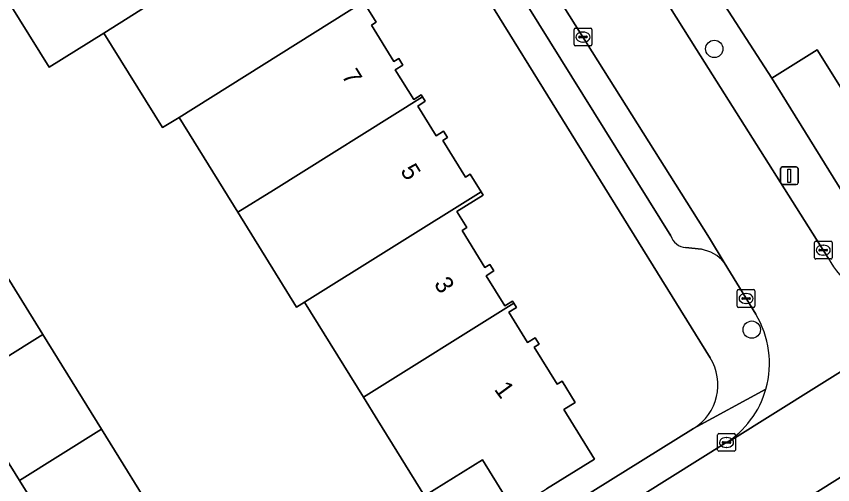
# Model space of a CAD drawing. Extents: x 157767 to 159172, y 387839 to 389425.
# Drawn here: x 158542.27 to 158588.4, y 388044.19 to 388070.65 of the extents above; entities that cross this region are included whole.
import ezdxf

# ---------------------------------------------------------------- set-up
doc = ezdxf.new("R2010")
doc.units = 0
for name, color, linetype in [('IMGEO_Boom', 7, 'Continuous'), ('IMGEO_Erf', 7, 'Continuous'), ('IMGEO_Kolk', 7, 'Continuous'), ('IMGEO_Lichtmast', 7, 'Continuous'), ('IMGEO_Pand', 7, 'Continuous'), ('IMGEO_Pand_nummerreeks', 7, 'Continuous'), ('IMGEO_Parkeervlak_open', 7, 'Continuous'), ('IMGEO_Rijbaan_lokaal_open', 7, 'Continuous'), ('IMGEO_Voetpad_open', 7, 'Continuous')]:
    doc.layers.add(name, color=color, linetype=linetype)

msp = doc.modelspace()

# ---------------------------------------------------------------- linework, layer by layer
at = {"layer": 'IMGEO_Boom'}
for centre in [(158581.714, 388068.809), (158583.832, 388052.949)]:
    msp.add_circle(centre, 0.489, dxfattribs=at)
at = {"layer": 'IMGEO_Erf'}
for points in [[(158581.483, 388051.362), (158560.399, 388085.371)], [(158570.354, 388042.793), (158568.615, 388045.599), (158565.338, 388043.57), (158562.706, 388047.821), (158561.891, 388049.137), (158558.564, 388054.508), (158558.102, 388054.219), (158554.783, 388059.578), (158551.465, 388064.936), (158550.538, 388064.358), (158547.208, 388069.7), (158544.119, 388067.774), (158540.75, 388073.178)], [(158561.897, 388071.468), (158562.608, 388070.322), (158562.335, 388070.153), (158563.614, 388068.09), (158563.885, 388068.258), (158564.111, 388067.894), (158563.687, 388067.629), (158564.729, 388065.948), (158565.153, 388066.21), (158565.22, 388066.102), (158565.379, 388065.846), (158564.953, 388065.581), (158565.995, 388063.9), (158566.42, 388064.163), (158566.646, 388063.797), (158566.374, 388063.628), (158567.652, 388061.566), (158567.924, 388061.734), (158568.541, 388060.738), (158568.661, 388060.545), (158567.174, 388059.625), (158567.738, 388058.716), (158567.463, 388058.545), (158568.755, 388056.462), (158569.028, 388056.632), (158569.257, 388056.262), (158568.827, 388055.996), (158569.88, 388054.298), (158570.308, 388054.564), (158570.383, 388054.442), (158570.537, 388054.194), (158570.107, 388053.928), (158571.16, 388052.23), (158571.588, 388052.496), (158571.816, 388052.127), (158571.541, 388051.956), (158572.833, 388049.873), (158573.108, 388050.042), (158573.852, 388048.842), (158573.206, 388048.442), (158574.944, 388045.637), (158572.223, 388043.951)], [(158606.501, 388070.878), (158607.378, 388069.481), (158602.662, 388066.524), (158602.252, 388066.267), (158599.852, 388070.093), (158595.508, 388067.368), (158595.241, 388067.201), (158594.284, 388068.725), (158589.446, 388065.691), (158587.528, 388068.75), (158584.968, 388067.145), (158590.08, 388058.884)], [(158540.442, 388058.034), (158543.761, 388052.683), (158547.077, 388047.335), (158550.419, 388041.947), (158555.234, 388034.183), (158556.403, 388032.356), (158573.012, 388042.677), (158580.545, 388047.358)]]:
    msp.add_lwpolyline(points, dxfattribs=at)
msp.add_arc((158579.008, 388049.83), 2.911, 301.8764, 31.7543, dxfattribs=at)
at = {"layer": 'IMGEO_Kolk'}
for p, q in [((158573.792, 388069.05), (158573.792, 388069.902)), ((158573.867, 388069.976), (158574.719, 388069.976)), ((158574.793, 388069.902), (158574.793, 388069.05)), ((158574.051, 388069.47), (158574.051, 388069.482)), ((158574.489, 388069.433), (158574.091, 388069.433)), ((158574.094, 388069.519), (158574.492, 388069.519)), ((158574.28, 388069.756), (158574.305, 388069.756)), ((158574.535, 388069.482), (158574.535, 388069.47)), ((158574.719, 388068.976), (158573.867, 388068.976)), ((158574.303, 388069.196), (158574.278, 388069.196)), ((158587.368, 388057.014), (158587.368, 388057.866)), ((158587.443, 388057.94), (158588.295, 388057.94)), ((158588.369, 388057.866), (158588.369, 388057.014)), ((158587.627, 388057.434), (158587.627, 388057.446)), ((158588.065, 388057.397), (158587.667, 388057.397)), ((158587.67, 388057.483), (158588.068, 388057.483)), ((158587.856, 388057.72), (158587.881, 388057.72)), ((158588.111, 388057.446), (158588.111, 388057.434)), ((158588.295, 388056.94), (158587.443, 388056.94)), ((158587.879, 388057.16), (158587.854, 388057.16)), ((158583.01, 388054.282), (158583.01, 388055.134)), ((158583.085, 388055.208), (158583.937, 388055.208)), ((158584.011, 388055.134), (158584.011, 388054.282)), ((158583.269, 388054.702), (158583.269, 388054.714)), ((158583.707, 388054.665), (158583.309, 388054.665)), ((158583.312, 388054.751), (158583.71, 388054.751)), ((158583.498, 388054.988), (158583.523, 388054.988)), ((158583.753, 388054.714), (158583.753, 388054.702)), ((158583.937, 388054.208), (158583.085, 388054.208)), ((158583.521, 388054.428), (158583.496, 388054.428)), ((158581.904, 388046.151), (158581.904, 388047.003)), ((158581.979, 388047.077), (158582.831, 388047.077)), ((158582.392, 388046.857), (158582.417, 388046.857)), ((158582.905, 388047.003), (158582.905, 388046.151)), ((158582.163, 388046.571), (158582.163, 388046.583)), ((158582.601, 388046.534), (158582.203, 388046.534)), ((158582.206, 388046.62), (158582.604, 388046.62)), ((158582.415, 388046.297), (158582.39, 388046.297)), ((158582.647, 388046.583), (158582.647, 388046.571)), ((158582.831, 388046.077), (158581.979, 388046.077))]:
    msp.add_line(p, q, dxfattribs=at)
for points in [[(158573.792, 388069.05), (158573.792, 388069.902)], [(158573.867, 388069.976), (158574.719, 388069.976)], [(158574.793, 388069.902), (158574.793, 388069.05)], [(158574.719, 388068.976), (158573.867, 388068.976)], [(158587.368, 388057.014), (158587.368, 388057.866)], [(158587.443, 388057.94), (158588.295, 388057.94)], [(158588.369, 388057.866), (158588.369, 388057.014)], [(158588.295, 388056.94), (158587.443, 388056.94)], [(158583.01, 388054.282), (158583.01, 388055.134)], [(158583.085, 388055.208), (158583.937, 388055.208)], [(158584.011, 388055.134), (158584.011, 388054.282)], [(158583.937, 388054.208), (158583.085, 388054.208)], [(158581.904, 388046.151), (158581.904, 388047.003)], [(158581.979, 388047.077), (158582.831, 388047.077)], [(158582.905, 388047.003), (158582.905, 388046.151)], [(158582.831, 388046.077), (158581.979, 388046.077)]]:
    msp.add_lwpolyline(points, dxfattribs=at)
for centre, radius, start, end in [((158573.869, 388069.9), 0.0765, 91.552, 178.448), ((158573.869, 388069.9), 0.0765, 91.552, 178.448), ((158574.717, 388069.9), 0.0765, 1.552, 88.448), ((158574.717, 388069.9), 0.0765, 1.552, 88.448), ((158574.091, 388069.479), 0.0403, 85.8775, 175.7526), ((158574.088, 388069.469), 0.0366, 178.938, 274.7102), ((158574.492, 388069.476), 0.043, 264.8664, 352.4533), ((158574.496, 388069.481), 0.0386, 1.7309, 96.639), ((158573.869, 388069.052), 0.0765, 181.552, 268.448), ((158573.869, 388069.052), 0.0765, 181.552, 268.448), ((158574.717, 388069.052), 0.0765, 271.552, 358.448), ((158574.717, 388069.052), 0.0765, 271.552, 358.448), ((158587.445, 388057.864), 0.0765, 91.552, 178.448), ((158587.445, 388057.864), 0.0765, 91.552, 178.448), ((158588.293, 388057.864), 0.0765, 1.552, 88.448), ((158588.293, 388057.864), 0.0765, 1.552, 88.448), ((158587.667, 388057.443), 0.0403, 85.8775, 175.7526), ((158587.664, 388057.433), 0.0366, 178.938, 274.7102), ((158588.068, 388057.44), 0.043, 264.8664, 352.4533), ((158588.072, 388057.445), 0.0386, 1.7309, 96.639), ((158587.445, 388057.016), 0.0765, 181.552, 268.448), ((158587.445, 388057.016), 0.0765, 181.552, 268.448), ((158588.293, 388057.016), 0.0765, 271.552, 358.448), ((158588.293, 388057.016), 0.0765, 271.552, 358.448), ((158583.087, 388055.132), 0.0765, 91.552, 178.448), ((158583.087, 388055.132), 0.0765, 91.552, 178.448), ((158583.935, 388055.132), 0.0765, 1.552, 88.448), ((158583.935, 388055.132), 0.0765, 1.552, 88.448), ((158583.309, 388054.711), 0.0403, 85.8775, 175.7526), ((158583.306, 388054.701), 0.0366, 178.938, 274.7102), ((158583.71, 388054.708), 0.043, 264.8664, 352.4533), ((158583.714, 388054.713), 0.0386, 1.7309, 96.639), ((158583.087, 388054.284), 0.0765, 181.552, 268.448), ((158583.087, 388054.284), 0.0765, 181.552, 268.448), ((158583.935, 388054.284), 0.0765, 271.552, 358.448), ((158583.935, 388054.284), 0.0765, 271.552, 358.448), ((158581.981, 388047.001), 0.0765, 91.552, 178.448), ((158581.981, 388047.001), 0.0765, 91.552, 178.448), ((158582.829, 388047.001), 0.0765, 1.552, 88.448), ((158582.829, 388047.001), 0.0765, 1.552, 88.448), ((158582.203, 388046.58), 0.0403, 85.8775, 175.7526), ((158582.2, 388046.57), 0.0366, 178.938, 274.7102), ((158582.604, 388046.577), 0.043, 264.8664, 352.4533), ((158582.608, 388046.582), 0.0386, 1.7309, 96.639), ((158581.981, 388046.153), 0.0765, 181.552, 268.448), ((158581.981, 388046.153), 0.0765, 181.552, 268.448), ((158582.829, 388046.153), 0.0765, 271.552, 358.448), ((158582.829, 388046.153), 0.0765, 271.552, 358.448)]:
    msp.add_arc(centre, radius, start, end, dxfattribs=at)
for centre, major_axis, ratio, start_param, end_param in [((158574.279, 388069.476), (-0.387, 0.002), 0.722429, 4.712389, 7.853982), ((158574.304, 388069.476), (-0.39, 0.002), 0.717154, 1.570796, 4.712389), ((158587.855, 388057.44), (-0.387, 0.002), 0.722429, 4.712389, 7.853982), ((158587.88, 388057.44), (-0.39, 0.002), 0.717154, 1.570796, 4.712389), ((158583.497, 388054.708), (-0.387, 0.002), 0.722429, 4.712389, 7.853982), ((158583.522, 388054.708), (-0.39, 0.002), 0.717154, 1.570796, 4.712389), ((158582.391, 388046.577), (-0.387, 0.002), 0.722429, 4.712389, 7.853982), ((158582.416, 388046.577), (-0.39, 0.002), 0.717154, 1.570796, 4.712389)]:
    msp.add_ellipse(centre, major_axis=major_axis, ratio=ratio, start_param=start_param, end_param=end_param, dxfattribs=at)
at = {"layer": 'IMGEO_Lichtmast'}
for p, q in [((158585.454, 388061.244), (158585.454, 388062.044)), ((158585.454, 388062.044), (158585.454, 388061.244)), ((158585.554, 388062.144), (158586.344, 388062.144)), ((158586.344, 388062.144), (158585.554, 388062.144)), ((158586.444, 388062.044), (158586.444, 388061.244)), ((158586.444, 388061.244), (158586.444, 388062.044)), ((158586.344, 388061.144), (158585.554, 388061.144)), ((158585.554, 388061.144), (158586.344, 388061.144))]:
    msp.add_line(p, q, dxfattribs=at)
msp.add_lwpolyline([(158585.874, 388062.019), (158586.024, 388062.019), (158586.024, 388061.269), (158585.874, 388061.269), (158585.874, 388062.019)], dxfattribs=at)
for centre, start, end in [((158585.554, 388062.044), 90, 180), ((158585.554, 388062.044), 90, 180), ((158586.344, 388062.044), 0, 90), ((158586.344, 388062.044), 360, 90), ((158585.554, 388061.244), 180, 270), ((158585.554, 388061.244), 180, 270), ((158586.344, 388061.244), 270, 0), ((158586.344, 388061.244), 270, 0)]:
    msp.add_arc(centre, 0.1, start, end, dxfattribs=at)
at = {"layer": 'IMGEO_Pand'}
for points in [[(158558.596, 388076.799), (158558.542, 388076.887), (158558.117, 388076.625), (158557.075, 388078.306), (158557.5, 388078.57), (158557.274, 388078.935), (158557.002, 388078.767), (158555.724, 388080.83), (158555.997, 388080.999), (158555.259, 388082.188), (158551.008, 388079.556), (158546.824, 388076.965), (158543.839, 388075.104), (158540.75, 388073.178), (158544.119, 388067.774), (158547.208, 388069.7), (158550.177, 388071.551)], [(158551.465, 388064.936), (158561.897, 388071.468), (158561.312, 388072.41), (158561.041, 388072.243), (158559.762, 388074.305), (158560.034, 388074.474), (158559.808, 388074.84), (158559.384, 388074.577), (158558.342, 388076.258), (158558.767, 388076.523), (158558.596, 388076.799), (158550.177, 388071.551), (158547.208, 388069.7), (158550.538, 388064.358)], [(158590.193, 388075.903), (158585.3, 388072.835), (158584.145, 388074.678), (158581.379, 388072.944), (158581.281, 388072.883), (158584.968, 388067.145), (158587.528, 388068.75), (158589.446, 388065.691), (158594.284, 388068.725), (158594.557, 388068.896)], [(158565.22, 388066.102), (158565.153, 388066.21), (158564.729, 388065.948), (158563.687, 388067.629), (158564.111, 388067.894), (158563.885, 388068.258), (158563.614, 388068.09), (158562.335, 388070.153), (158562.608, 388070.322), (158561.897, 388071.468), (158551.465, 388064.936), (158554.783, 388059.578), (158556.813, 388060.835)], [(158568.541, 388060.738), (158567.924, 388061.734), (158567.652, 388061.566), (158566.374, 388063.628), (158566.646, 388063.797), (158566.42, 388064.163), (158565.995, 388063.9), (158564.953, 388065.581), (158565.379, 388065.846), (158565.22, 388066.102), (158556.813, 388060.835), (158554.783, 388059.578), (158558.102, 388054.219), (158558.564, 388054.508)], [(158570.383, 388054.442), (158570.308, 388054.564), (158569.88, 388054.298), (158568.827, 388055.996), (158569.257, 388056.262), (158569.028, 388056.632), (158568.755, 388056.462), (158567.463, 388058.545), (158567.738, 388058.716), (158567.174, 388059.625), (158568.661, 388060.545), (158568.541, 388060.738), (158558.564, 388054.508), (158561.891, 388049.137)], [(158539.118, 388049.775), (158543.761, 388052.683), (158540.442, 388058.034), (158535.788, 388055.115)], [(158570.383, 388054.442), (158561.891, 388049.137), (158562.706, 388047.821), (158565.338, 388043.57), (158568.615, 388045.599), (158570.354, 388042.793), (158572.223, 388043.951), (158574.944, 388045.637), (158573.206, 388048.442), (158573.852, 388048.842), (158573.108, 388050.042), (158572.833, 388049.873), (158571.541, 388051.956), (158571.816, 388052.127), (158571.588, 388052.496), (158571.16, 388052.23), (158570.107, 388053.928), (158570.537, 388054.194)], [(158542.447, 388044.435), (158547.077, 388047.335), (158543.761, 388052.683), (158539.118, 388049.775)], [(158542.447, 388044.435), (158545.856, 388038.968), (158550.419, 388041.947), (158547.077, 388047.335)]]:
    msp.add_lwpolyline(points, close=True, dxfattribs=at)
at = {"layer": 'IMGEO_Parkeervlak_open'}
for points in [[(158582.268, 388056.746), (158581.434, 388058.111), (158570.744, 388075.126), (158569.941, 388076.402), (158568.599, 388078.534), (158562.853, 388087.665)], [(158563.093, 388084.206), (158579.251, 388058.252)], [(158580.093, 388057.584), (158580.982, 388057.488)]]:
    msp.add_lwpolyline(points, dxfattribs=at)
for centre, radius, start, end in [((158580.172, 388058.548), 0.967, 197.8173, 265.3293), ((158580.594, 388055.33), 2.193, 40.2258, 79.8058)]:
    msp.add_arc(centre, radius, start, end, dxfattribs=at)
at = {"layer": 'IMGEO_Rijbaan_lokaal_open'}
for points in [[(158580.717, 388068.777), (158574.233, 388079.1), (158569.941, 388076.402), (158570.744, 388075.126), (158581.434, 388058.111), (158582.268, 388056.746), (158584.053, 388053.823)], [(158588.162, 388056.973), (158580.717, 388068.777)], [(158582.332, 388046.529), (158582.556, 388046.64), (158595.192, 388054.536)], [(158541.291, 388022.91), (158556.403, 388032.356), (158555.234, 388034.183), (158549.918, 388030.869), (158547.042, 388035.482), (158547.753, 388035.925), (158545.856, 388038.968), (158542.447, 388044.435), (158539.118, 388049.775)]]:
    msp.add_lwpolyline(points, dxfattribs=at)
msp.add_lwpolyline([(158602.47, 388053.168), (158607.134, 388056.097), (158604.468, 388060.381), (158598.186, 388056.371), (158595.192, 388054.536), (158582.556, 388046.64), (158582.332, 388046.529), (158565.577, 388036.046), (158560.3, 388032.761), (158562.987, 388028.446), (158574.586, 388035.66), (158586.389, 388043.071)], close=True, dxfattribs=at)
for centre, radius, start, end in [((158593.035, 388059.692), 5.58, 209.1561, 231.9393), ((158579.495, 388051.045), 5.338, 344.2276, 31.3644), ((158579.509, 388051.043), 5.324, 302.0232, 344.2071)]:
    msp.add_arc(centre, radius, start, end, dxfattribs=at)
at = {"layer": 'IMGEO_Voetpad_open'}
for points in [[(158543.728, 388114.955), (158550.45, 388104.152), (158551.851, 388101.897), (158553.86, 388098.665), (158555.739, 388095.641), (158557.163, 388093.348), (158558.904, 388090.545), (158556.64, 388089.139), (158554.172, 388087.608), (158555.818, 388084.922), (158556.878, 388083.191), (158560.399, 388085.371), (158581.483, 388051.362)], [(158579.251, 388058.252), (158563.093, 388084.206)], [(158584.968, 388067.145), (158581.281, 388072.883), (158581.379, 388072.944), (158574.516, 388084.034), (158572.668, 388082.532), (158572.243, 388082.269), (158572.893, 388081.234), (158574.233, 388079.1), (158580.717, 388068.777), (158588.162, 388056.973)], [(158590.08, 388058.884), (158584.968, 388067.145)], [(158545.154, 388012.431), (158548.372, 388014.479), (158586.39, 388038.074), (158587.736, 388040.994), (158612.65, 388056.606), (158611.489, 388058.243), (158610.518, 388057.633), (158610.247, 388058.053), (158609.497, 388057.581), (158607.134, 388056.097), (158602.47, 388053.168), (158586.389, 388043.071)], [(158580.982, 388057.488), (158580.093, 388057.584)], [(158584.053, 388053.823), (158582.268, 388056.746)], [(158584.632, 388049.594), (158580.545, 388047.358), (158573.012, 388042.677), (158556.403, 388032.356), (158557.4, 388032.182), (158557.948, 388031.298), (158560.3, 388032.761), (158565.577, 388036.046)], [(158580.545, 388047.358), (158584.632, 388049.594)], [(158565.577, 388036.046), (158582.332, 388046.529)]]:
    msp.add_lwpolyline(points, dxfattribs=at)
for centre, radius, start, end in [((158580.172, 388058.548), 0.967, 197.8173, 265.3293), ((158580.594, 388055.33), 2.193, 40.2258, 79.8058), ((158593.035, 388059.692), 5.58, 209.1561, 231.9393), ((158579.495, 388051.045), 5.338, 344.2276, 31.3644), ((158579.008, 388049.83), 2.911, 301.8764, 31.7543), ((158579.509, 388051.043), 5.324, 302.0232, 344.2071)]:
    msp.add_arc(centre, radius, start, end, dxfattribs=at)

# ---------------------------------------------------------------- texts
at = {"layer": 'IMGEO_Pand_nummerreeks'}
for s, rotation, p in [('7', 301.7668, (158560.627, 388067.289)), ('5', 301.7646, (158563.947, 388061.927)), ('3', 301.7646, (158565.845, 388055.541)), ('1', 306.3655, (158569.243, 388049.57))]:
    msp.add_text(s, height=1, rotation=rotation, dxfattribs=at).set_placement(p)

doc.saveas('drawing.dxf')
